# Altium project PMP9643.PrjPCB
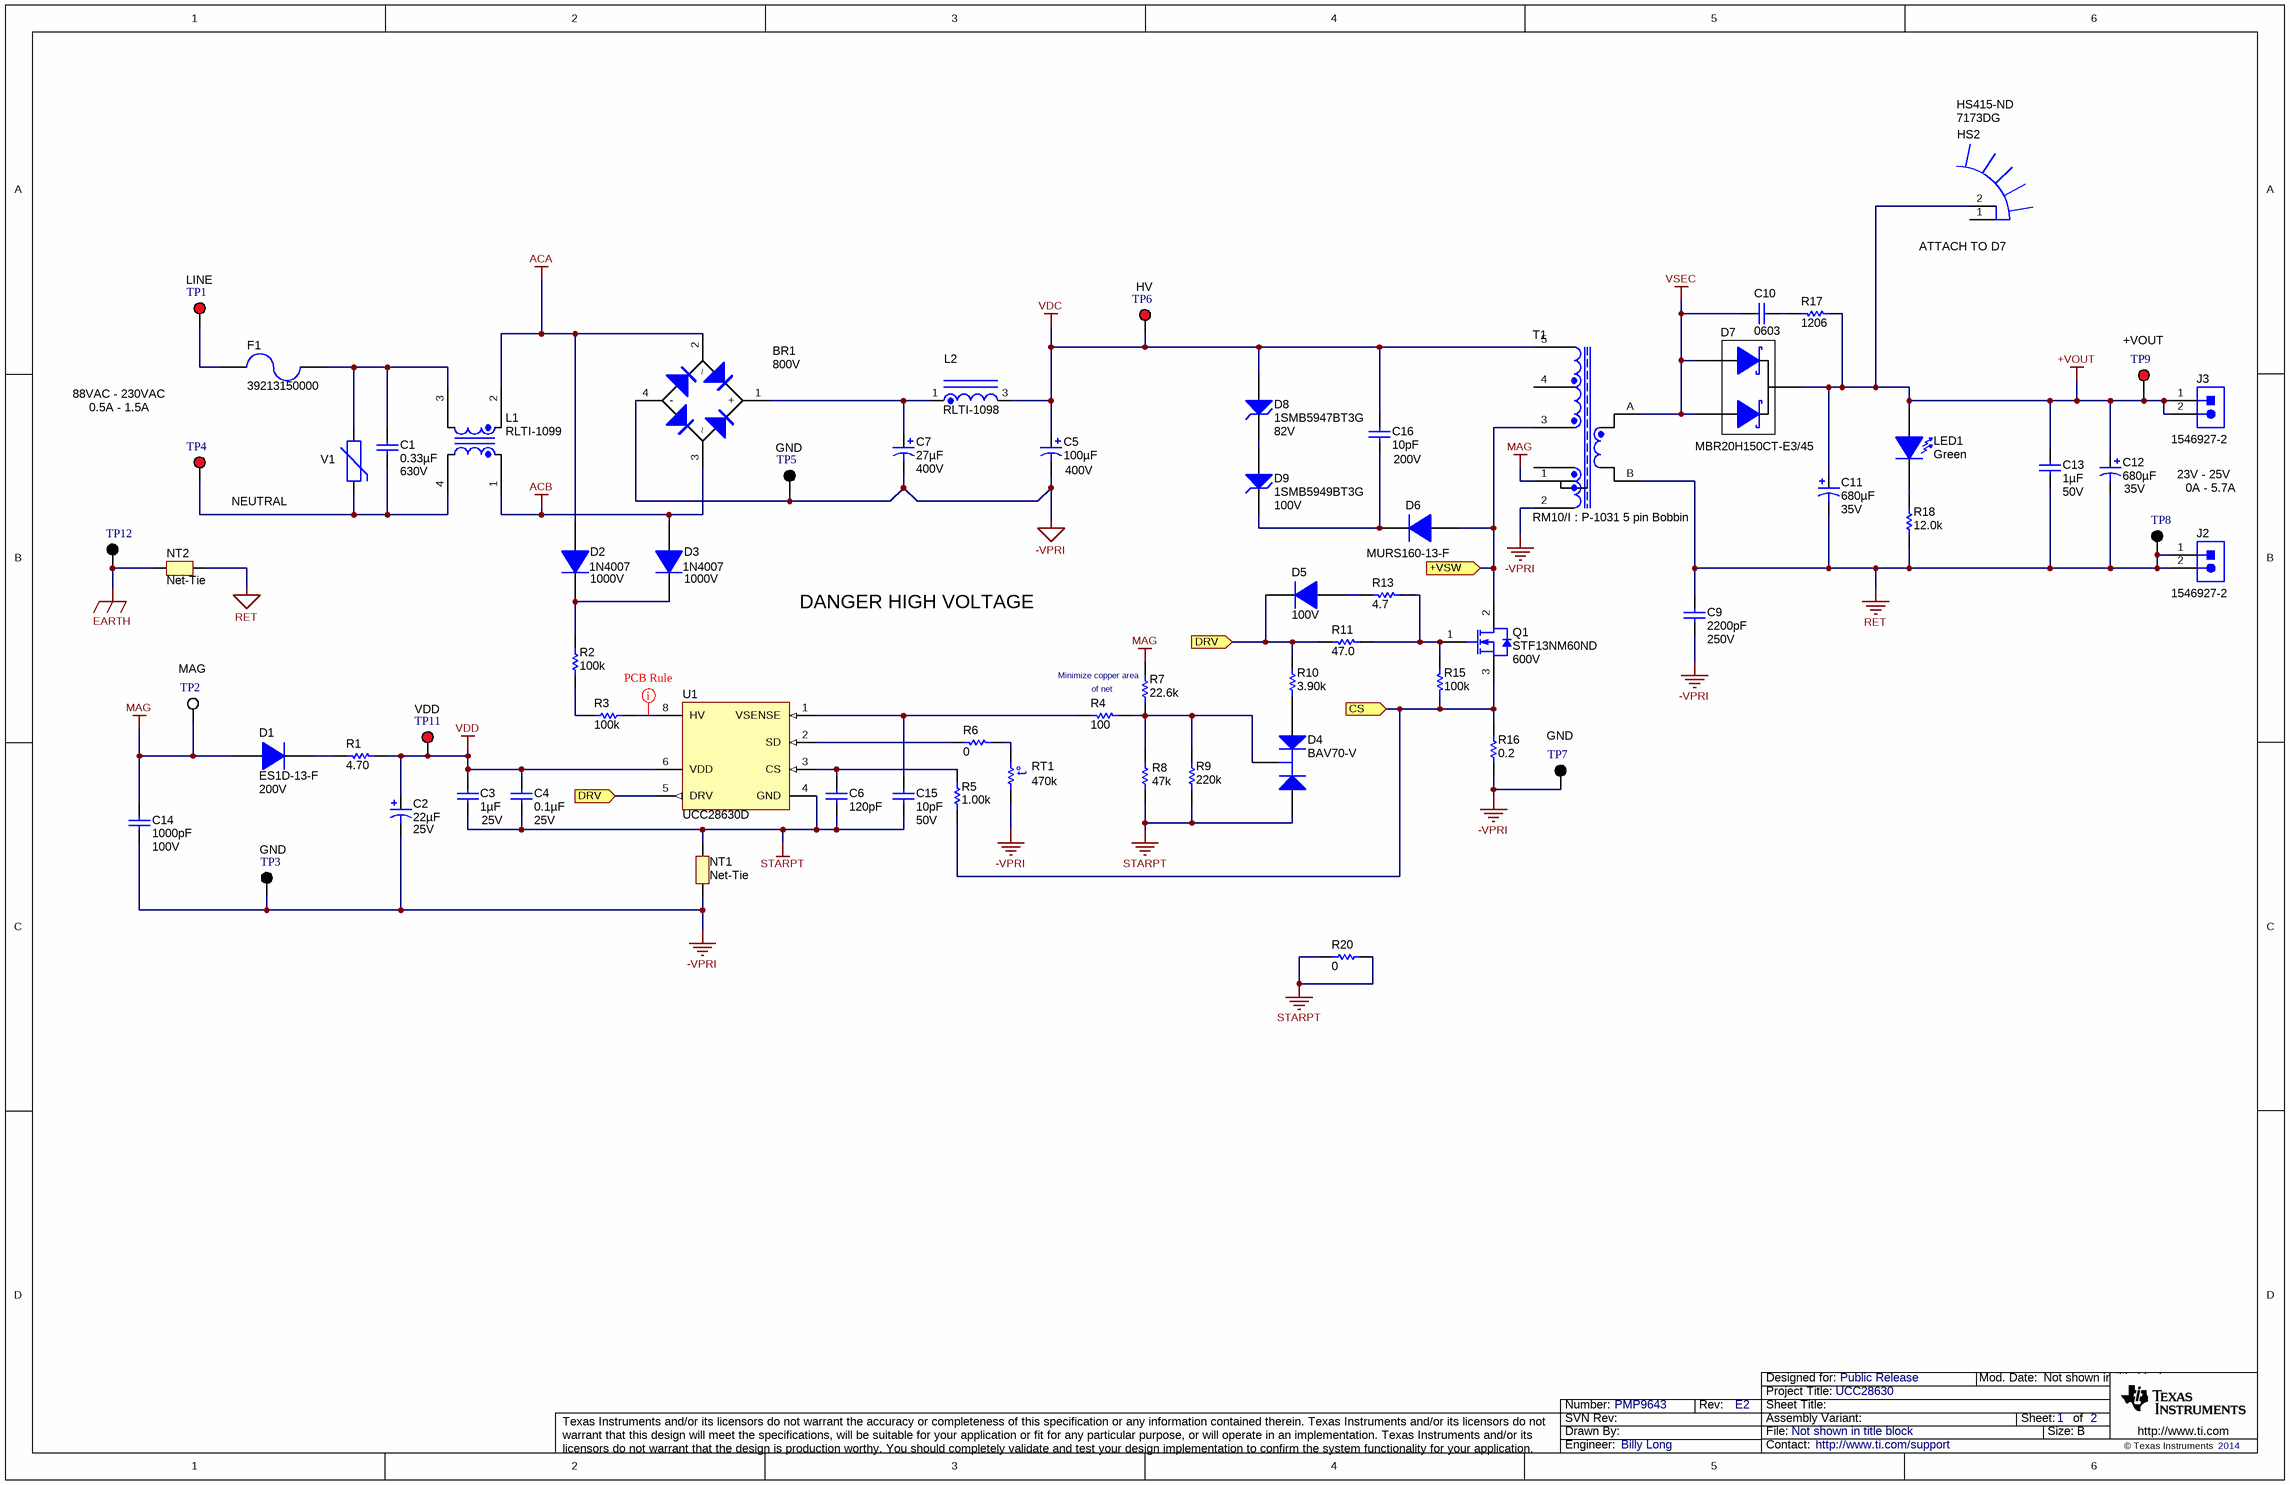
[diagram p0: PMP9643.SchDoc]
TechSupport: http://www.ti.com/support; SCH_Rev: E2; PRJ_Title: UCC28630; PRJ_Number: PMP9643; PRJ_Engineer: Billy Long; PRJ_Customer: Public Release; PCB_Rev: E2; PCB_Layout: Brian Gaynor; CopyrightYear: 2014
2 sheets, 91 parts. Net scope: flat (ports and power ports of the same name join across sheets).
Board file: PMP9643.PcbDoc
Sheets:
  PMP9643.SchDoc
  PMP9643HW.SchDoc

## Sheet PMP9643.SchDoc
size 431 x 279 mm; Date: Not shown in title block; ApprovedBy: Not shown in title block; CheckedBy: Not shown in title block; Author: Not shown in title block; CompanyName: Not shown in title block; Engineer: Not shown in title block; Organization: Not shown in title block; Address1: Not shown in title block; Address2: Not shown in title block; Address3: Not shown in title block; Address4: Not shown in title block; DocumentNumber: 1; Revision: Use project parameter SCH_Rev; SheetNumber: 1; SheetTotal: 2; PageSetup: Record=PageOptions|CenterHorizontal=True|CenterVertical=True|PrintScale=0.94|XCorrection=1.00|YCorrection=1.00|PrintKind=0|BorderSize=5000000|LeftOffset=0|BottomOffset=0|Orientation=2|PaperLength=4200|PaperWidth=2970|Scale=100|PaperSource=7|PrintQuality=600|MediaType=1|DitherType=10|PaperKind=A3|PrintScaleMode=1

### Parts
BR1  value 800V  [GBU]  (hidden comment: GBU4K-E3/45)
C1  ValueDisplayed: 0.33µF  Value2: 630V  [CAPRR1500W80D1750T1000H1650]  (hidden comment: BFC233840334)
C2  ValueDisplayed: 22µF  Value2: 25V  [ML_500x500]  (hidden comment: 25ML22MEFC5X5)
C3  ValueDisplayed: 1µF  Value2: 25V  [1206]  (hidden comment: 12063C105KAT2A)
C4  ValueDisplayed: 0.1µF  Value2: 25V  [0603]  (hidden comment: C0603C104K3RACTU)
C5  ValueDisplayed: 100µF  Value2: 400V  [CAPPR750W80D1600H3000]  (hidden comment: 400KXW100MEFC16X30)
C6  ValueDisplayed: 120pF  [0603]  (hidden comment: 06035A121JAT2A)
C7  ValueDisplayed: 27µF  Value2: 400V  [CY_1250x2000]  (hidden comment: UCY2G270MHD1TO)
C9  ValueDisplayed: 2200pF  Value2: 250V  [CAPRD1000W60D1000H1400]  (hidden comment: DE1E3KX222MA5BA01)
C10  0603YC823KAT2A  [0603]  (value not drawn)
C11  ValueDisplayed: 680µF  Value2: 35V  [HW_10x20]  (hidden comment: UHW1V681MPD6)
C12  ValueDisplayed: 680µF  Value2: 35V  [HW_10x20]  (hidden comment: UHW1V681MPD6)
C13  ValueDisplayed: 1µF  Value2: 50V  [0805_HV]  (hidden comment: 08055C105KAT2A)
C14  ValueDisplayed: 1000pF  Value2: 100V  [0805_HV]  (hidden comment: 08051C102KAT2A)
C15  ValueDisplayed: 10pF  Value2: 50V  [0603]  (hidden comment: 06035A100JAT2A)
C16  ValueDisplayed: 10pF  Value2: 200V  [1206]  (hidden comment: 12062A100JAT2A)
D1  value 200V  [SMA]  (hidden comment: ES1D-13-F)
D2  1N4007  value 1000V  [DO-41]
D3  1N4007  value 1000V  [DO-41]
D4  BAV70-V  [SOT-23]
D5  value 100V  [sod-323]  (hidden comment: BAS316,115)
D6  MURS160-13-F  [SMB]
D7  MBR20H150CT-E3/45  [TO-220AB_100mil]
D8  1SMB5947BT3G  value 82V  [SMB]
D9  1SMB5949BT3G  value 100V  [SMB]
F1  39213150000  [FUSE_392]
HS2  7173DG  Supplier Part Number 1: HS415-ND  [HSINK_7173DG]
J2  1546927-2  [TE-1546927-2]
J3  1546927-2  [TE-1546927-2]
L1  RLTI-1099  [RLTI-1099]
L2  RLTI-1098  [RLTI-1098]
LED1  value Green  [LED_HLMP1523]  (hidden comment: HLMP1523)
NT1  Net-Tie  [Net-Tie_10mil]  (net tie, no BOM)
NT2  Net-Tie  [Net-Tie_10mil]  (net tie, no BOM)
Q1  STF13NM60ND  value 600V  [TO-220_FullPAK_Offset]
R1  value 4.70  [0805_HV]  (hidden comment: ERJ-6RQF4R7V)
R2  value 100k  [1206]  (hidden comment: RC1206FR-07100KL)
R3  value 100k  [1206]  (hidden comment: RC1206FR-07100KL)
R4  value 100  [0603]  (hidden comment: CRCW0603100RFKEA)
R5  value 1.00k  [0603]  (hidden comment: CRCW06031K00FKEA)
R6  value 0  [0603]  (hidden comment: CRCW06030000Z0EA)
R7  value 22.6k  [1206]  (hidden comment: CRCW120622K6FKEA)
R8  value 47k  [1206]  (hidden comment: CRCW120647K0FKEA)
R9  value 220k  [0603]  (hidden comment: RC0603FR-07220KL)
R10  value 3.90k  [0603]  (hidden comment: RC0603FR-073K9L)
R11  value 47.0  [1206]  (hidden comment: RC1206FR-0747RL)
R13  value 4.7  [1206]  (hidden comment: CRCW12064R70JNEA)
R15  value 100k  [0603]  (hidden comment: CRCW0603100KFKEA)
R16  value 0.2  [2512M]  (hidden comment: CSRN2512FKR200)
R17  CRCW12061K00FKEA  [1206]  (value not drawn)
R18  value 12.0k  [1206]  (hidden comment: RC1206FR-0712KL)
R20  value 0  [1206]  (hidden comment: CRCW12060000Z0EA)
RT1  value 470k  [THERM_B57164K]  (hidden comment: B57164K474J)
T1  RM10/I : P-1031 5 pin Bobbin  [RM10-5pin]
TP1  5005  [Keystone5005]  (value not drawn)
TP2  5007  [Keystone5007]  (value not drawn)
TP3  5006  [Keystone5006]  (value not drawn)
TP4  5005  [Keystone5005]  (value not drawn)
TP5  5006  [Keystone5006]  (value not drawn)
TP6  5005  [Keystone5005]  (value not drawn)
TP7  5006  [Keystone5006]  (value not drawn)
TP8  5006  [Keystone5006]  (value not drawn)
TP9  5005  [Keystone5005]  (value not drawn)
TP11  5005  [Keystone5005]  (value not drawn)
TP12  5006  [Keystone5006]  (value not drawn)
U1  UCC28630D  [D0007A_N]
V1  B72214S0271K101  [VAR_B72214S0271]  (value not drawn)

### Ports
+VSW, CS, DRV

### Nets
+VOUT: C11.1(+) C12.1(+) C13.2 D7.2(K) HS2.2 J3.1 J3.2 LED1.1(A) R17.1 TP9.1
-VPRI: BR1.4(-) C2.2(-) C5.2(-) C7.2(-) C9.2 C14.2 NT1.2 R16.1 RT1.1 T1.2 TP3.1 TP5.1 TP7.1
ACA: BR1.2 D2.2(A) L1.2
ACB: BR1.3 D3.2(A) L1.1
EARTH: NT2.1 TP12.1
MAG: C14.1 D1.2(A) R7.1 T1.1 TP2.1
RET: C9.1 C11.2(-) C12.2(-) C13.1 J2.1 J2.2 NT2.2 R18.1 T1.B TP8.1
STARPT: C3.2 C4.2 C6.2 C15.1 D4.2(K) NT1.1 R8.1 R9.1 R20.1 R20.2 U1.4(GND)
VDC: C5.1(+) C16.2 D8.2(A) L2.3 T1.5 TP6.1
VDD: C2.1(+) C3.1 C4.1 R1.1 TP11.1 U1.6(VDD)
VSEC: C10.2 D7.1(A) D7.3(A) T1.A
+VSW: D6.2(A) Q1.2(D) T1.3 ; port +VSW
CS: Q1.3(S) R5.1 R15.1 R16.2 ; port CS
DRV: D5.1(K) R10.2 R11.2 U1.5(DRV) ; port DRV
NetBR1_1: BR1.1(+) C7.1(+) L2.1
NetC1_1: C1.1 L1.4 TP4.1 V1.2
NetC1_2: C1.2 F1.1 L1.3 V1.1
NetC6_1: C6.1 R5.2 U1.3(CS)
NetC10_1: C10.1 R17.2
NetC15_2: C15.2 R4.2 U1.1(VSENSE)
NetC16_1: C16.1 D6.1(K) D9.1(K)
NetD1_1: D1.1(K) R1.2
NetD2_1: D2.1(K) D3.1(K) R2.2
NetD4_1: D4.1(A) R10.1
NetD4_3: D4.3(C) R4.1 R7.2 R8.2 R9.2
NetD5_2: D5.2(A) R13.2
NetD8_1: D8.1(K) D9.2(A)
NetF1_2: F1.2 TP1.1
NetLED1_2: LED1.2(K) R18.2
NetQ1_1: Q1.1(G) R11.1 R13.1 R15.2
NetR2_1: R2.1 R3.2
NetR3_1: R3.1 U1.8(HV)
NetR6_1: R6.1 U1.2(SD)
NetR6_2: R6.2 RT1.2

Not connected (* = marked no-connect by the designer): HS2 1; T1 4

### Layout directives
rule Clearance Constraint [Clearance = 1mm]: NetR3_1

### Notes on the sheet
- (near TP1) LINE
- (near TP6) HV
- (near HS2) ATTACH TO D7
- (near TP9) +VOUT
- 88VAC - 230VAC
- 0.5A - 1.5A
- NEUTRAL
- GND
- 23V - 25V
- 0A - 5.7A
- DANGER HIGH VOLTAGE
- (near TP2) MAG
- (near TP11) VDD
- (near R7) Minimize copper area
- of net
- (near TP7) GND
- (near TP3) GND

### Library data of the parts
BR1 = GBU4K-E3/45: Diode, Switching-Bridge, 800V, 4A, TH; Manufacturer: Vishay-Semiconductor; U/M: EA; Vf_V: 1; Value2: 1V; Io_A: 4; Vr_V: 800; TJmax_C: 150; RJC_CperW: 4.2
C1 = BFC233840334: CAP, Film, 0.33uF, 630V, +/-20%, TH; Manufacturer: Vishay-Bccomponents; Polarized: N; CompType: Capacitor; U/M: EA; Cap_F: 0.00000033; Tolerance_%: 20; Value1: Unknown; VDC_V: 630; TaMin_C: -55; TaMax_C: 105; Cap_Case: 17.5x16.5x10mm
C2 = 25ML22MEFC5X5: CAP, AL, 22uF, 25V, +/-20%, TH; Manufacturer: Rubycon; Polarized: Y; CompType: Capacitor; U/M: EA; Cap_F: 0.000022; Tolerance_%: 20; Value1: Unknown; VDC_V: 25; IRMS_A: 0.042; TaMin_C: -40; TaMax_C: 105; Cap_Case: 5x5
C3 = 12063C105KAT2A: CAP, CERM, 1uF, 25V, +/-10%, X7R, 1206; Manufacturer: AVX; Polarized: N; CompType: Capacitor; U/M: EA; Cap_F: 0.000001; Tolerance_%: 10; ESR_Ohm: 0.013; Value1: 0.013 ohm; VDC_V: 25; TaMin_C: -55; TaMax_C: 125
C4 = C0603C104K3RACTU: CAP, CERM, 0.1uF, 25V, +/-10%, X7R, 0603; Manufacturer: Kemet; Polarized: N; CompType: Capacitor; U/M: EA; Cap_F: 0.0000001; Tolerance_%: 10; Value1: Unknown; VDC_V: 25; TaMin_C: -55; TaMax_C: 125
C5 = 400KXW100MEFC16X30: CAP, AL, 100uF, 400V, +/-20%, TH; Manufacturer: Rubycon; Polarized: Y; CompType: Capacitor; U/M: EA; Cap_F: 0.0001; Tolerance_%: 20; Value1: Unknown; VDC_V: 400; IRMS_A: 0.58; TaMin_C: -25; TaMax_C: 105; Cap_Case: RCAP, 16x30mm
C6 = 06035A121JAT2A: CAP, CERM, 120pF, 50V, +/-5%, C0G/NP0, 0603; Manufacturer: AVX; Polarized: N; CompType: Capacitor; U/M: EA; Cap_F: 0.00000000012; Tolerance_%: 5; ESR_Ohm: 0.109; Value1: 0.109 ohm; VDC_V: 50; TaMin_C: -55; TaMax_C: 125
C7 = UCY2G270MHD1TO: CAP, AL, 27uF, 400V, +/-20%, TH; Manufacturer: Nichicon; Tolerance_%: 20; VDC_V: 400; Polarized: Y; CompType: Capacitor; U/M: EA; Cap_F: 0.000027; Value1: Unknown; IRMS_A: 0.36; TaMin_C: -40; TaMax_C: 105; Cap_Case: 12.5x20
C9 = DE1E3KX222MA5BA01: CAP, CERM, 2200pF, 250V, +/-20%, E, Disc 10x8mm; Manufacturer: MuRata; VDC_V: 250; Tolerance_%: 20; Polarized: N; CompType: Capacitor; U/M: EA; Cap_F: 0.0000000022; Value1: Unknown; TaMin_C: -25; TaMax_C: 85
C10 = 0603YC823KAT2A: CAP, CERM, 0.082uF, 16V, +/-10%, X7R, 0603; Manufacturer: AVX; Polarized: N; CompType: Capacitor; ValueDisplayed: 0.082µF; U/M: EA; Cap_F: 0.000000082; Tolerance_%: 10; ESR_Ohm: 0.042; Value1: 0.042 ohm; VDC_V: 16; TaMin_C: -55; TaMax_C: 125
C11 = UHW1V681MPD6: CAP, AL, 680uF, 35V, +/-20%, 0.019 ohm, TH; Manufacturer: Nichicon; Tolerance_%: 20; VDC_V: 35; ESR_Ohm: 0.019; Polarized: Y; CompType: Capacitor; U/M: EA; Cap_F: 0.00068; IRMS_A: 2.5; TaMin_C: -40; TaMax_C: 105; Cap_Case: 10x20
C12 = UHW1V681MPD6: CAP, AL, 680uF, 35V, +/-20%, 0.019 ohm, TH; Manufacturer: Nichicon; Polarized: Y; CompType: Capacitor; U/M: EA; Cap_F: 0.00068; Tolerance_%: 20; VDC_V: 35; ESR_Ohm: 0.019; IRMS_A: 2.5; TaMin_C: -40; TaMax_C: 105; Cap_Case: 10x20
C13 = 08055C105KAT2A: CAP, CERM, 1uF, 50V, +/-10%, X7R, 0805; Manufacturer: AVX; Polarized: N; CompType: Capacitor; U/M: EA; Cap_F: 0.000001; Tolerance_%: 10; Value1: Unknown; VDC_V: 50; TaMin_C: -55; TaMax_C: 125; Cap_Case: 0805
C14 = 08051C102KAT2A: CAP, CERM, 1000pF, 100V, +/-10%, X7R, 0805; Manufacturer: AVX; Polarized: N; CompType: Capacitor; U/M: EA; Cap_F: 0.000000001; Tolerance_%: 10; ESR_Ohm: 0.29; Value1: 0.29 ohm; VDC_V: 100; TaMin_C: -55; TaMax_C: 125; Cap_Case: 0805
C15 = 06035A100JAT2A: CAP, CERM, 10pF, 50V, +/-5%, C0G/NP0, 0603; Manufacturer: AVX; Polarized: N; CompType: Capacitor; U/M: EA; Cap_F: 0.00000000001; Tolerance_%: 5; ESR_Ohm: 0.403; Value1: 0.403 ohm; VDC_V: 50; TaMin_C: -55; TaMax_C: 125
C16 = 12062A100JAT2A: CAP, CERM, 10pF, 200V, +/-5%, C0G/NP0, 1206; Manufacturer: AVX; Polarized: N; CompType: Capacitor; U/M: EA; Cap_F: 0.00000000001; Tolerance_%: 5; Value1: Unknown; VDC_V: 200; TaMin_C: -55; TaMax_C: 125
D1 = ES1D-13-F: Diode, Ultrafast, 200V, 1A, SMA; Manufacturer: Diodes Inc.; U/M: EA; Vf_V: 0.92; Value2: 0.92V; Io_A: 1; Vr_V: 200; TJmax_C: 150; RJC_CperW: 25
D2 D3 = 1N4007: Diode, P-N, 1000V, 1A, TH; Manufacturer: Fairchild Semiconductor; U/M: EA; Vf_V: 1.1; Value2: 1.1V; Io_A: 1; Vr_V: 1000; TJmax_C: 175; RJC_CperW: 50
D4 = BAV70-V: Diode, Switching, 70V, 0.25A, SOT-23; Manufacturer: Vishay-Semiconductor; SymbolCreator: a0412235; U/M: EA; Vf_V: 1.25; Value2: 1.25V; Io_A: 0.25; Vr_V: 70; TJmax_C: 150; RJC_CperW: 430
D5 = BAS316,115: Diode, Ultrafast, 100V, 0.25A, SOD-323; Manufacturer: NXP Semiconductor; U/M: EA; Vf_V: 1.4; Value2: 1.4V; Io_A: 0.25; Vr_V: 100; TJmax_C: 150
D6 = MURS160-13-F: Diode, Ultrafast, 600V, 1A, SMB; Manufacturer: Diodes Inc.; U/M: EA; Vf_V: 1.25; Value2: 1.25V; Io_A: 1; Vr_V: 600; TJmax_C: 150; RJC_CperW: 13
D7 = NTST30100CTG: Manufacturer: Vishay Semiconductor Diodes Division; Vr_V: 150V; Speed: Fast Recovery =< 500ns, > 200mA (Io); Type: Schottky; Value: 900mV @ 10A; Description: DIODE SCHOTTKY 150V 10A TO220AB; Diode Configuration: 1 Pair Common Cathode; Current - Reverse Leakage @ Vr: 5µA @ 150V; Current - Average Rectified (Io) (per Diode): 10A
D8 = 1SMB5947BT3G: Diode, Zener, 82V, 550mW, SMB; Manufacturer: ON Semiconductor; U/M: EA; Power_W: 0.55; Vz_V: 82; Value1: 0.55W; RJA_CperW: 226
D9 = 1SMB5949BT3G: Diode, Zener, 100V, 550mW, SMB; Manufacturer: ON Semiconductor; U/M: EA; Power_W: 0.55; Vz_V: 100; Value1: 0.55W; RJA_CperW: 226
F1 = 39213150000: Fuse, 3.15A, 250V, TH; Manufacturer: Littelfuse; U/M: EA; OpeningTime_200%_max: 120; VDC_V: 250; Irating_A: 3.15; Vdrop: 0.08; Soldering_Wave_MaxTemp_C: 260; Soldering_Wave_MaxTime_s: 5
HS2 = 7173DG: BOARD LEVEL HEATSINK .375" TO-220; Manufacturer: Aavid Thermalloy; Attachment Method: Bolt On and PC Pin; Material Finish: Tin; Thermal Resistance @ Natural: 25.8°C/W; Thermal Resistance @ Forced Air Flow: 10.0°C/W @ 200 LFM; Power Dissipation @ Temperature Rise: 1.5W @ 50°C; Shape: Rectangular
J2 J3 = TE-1546927-2: Manufacturer: TE Connectivity; Pitch: 0.325" (8.26mm); Number of Wire Entries: 2; Bottom Termination: PC Pin; Top Termination: Screws with Captive Plate; VDC_V: 300V; Material - Insulation: Polybutylene Terephthalate (PBT); Current Rating: 15A; Wire Gauge: 14-22 AWG; Material Flammability Rating: UL94 V-0; Barrier Type: 3 Wall (Tri); Description: CONN BARRIER BLOCK 2CIRC 8.26MM
L1 = RLTI-1099: Inductor, Toroid, ?, 4.5mH, A, 0.05 ohm, TH; Manufacturer: Renco Electronics; SymbolCreator: a0799628; Ind_H: 4.5E-3; Irms: 25A @ C rise; DCR_ohm: 0.05; U/M: EA
L2 = RLTI-1098: Inductor, Toroid, ?, 47.7uH, A, 0.04 ohm, TH; Manufacturer: Renco Electronics; ValueDisplayed: 47.7µH; SymbolCreator: x0208326; Ind_H: 47.7E-6; Irms: 25A @ C rise; DCR_ohm: 0.04; U/M: EA
LED1 = HLMP1523: LED, Green, TH; Manufacturer: Everlight; Vf_V: 2.2; Value2: 2.2V; Io_A: 0.02; Tjmax_C: 100; Value1: W; U/M: EA
NT1 NT2 = Net-Tie: Single point connection between nets.; SymbolCreator: codlsc
Q1 = STF13NM60ND: MOSFET, N-CH, 600V, 11A, TO-220 FullPAK; Manufacturer: ST Microelectronics; Alternate Manufacturer: None; U/M: EA; ChType: N; VdsMax_V: 600; Value1: ? ohm; Value2: 24.5 nC; QgTyp_nC: 24.5; Vgs_V: 25; IdsMax_A: 11
R1 = ERJ-6RQF4R7V: RES, 4.70 ohm, 1%, 0.125W, 0805; Manufacturer: Panasonic; CompType: Resistor; TempCo: 200 ppm/C; Tolerance_%: 1; Power_W: 0.125; Res_ohm: 4.7; Value_Code: 4R70; U/M: EA
R2 R3 = RC1206FR-07100KL: RES, 100k ohm, 1%, 0.25W, 1206; Manufacturer: Yageo America; CompType: Resistor; Res_ohm: 100000; Tolerance_%: 1; Power_W: 0.25; VDC_V: 200; TempCo: 100 ppm/C; EIA_Code: E96; U/M: EA
R4 = CRCW0603100RFKEA: RES, 100 ohm, 1%, 0.1W, 0603; Manufacturer: Vishay-Dale; CompType: Resistor; Value_Code: 100R; Tolerance_%: 1; Power_W: 0.1; VDC_V: 75; TempCo: 100 ppm/C; EIA_Code: E96; U/M: EA
R5 = CRCW06031K00FKEA: RES, 1.00k ohm, 1%, 0.1W, 0603; Manufacturer: Vishay-Dale; CompType: Resistor; Res_ohm: 1000; Value_Code: 1k00; Tolerance_%: 1; Power_W: 0.1; VDC_V: 75; TempCo: 100 ppm/C; EIA_Code: E96; U/M: EA
R6 = CRCW06030000Z0EA: RES, 0 ohm, 5%, 0.1W, 0603; Manufacturer: Vishay-Dale; CompType: Resistor; Value_Code: 0000; Tolerance_%: 5; Power_W: 0.1; VDC_V: 75; TempCo: 200 ppm/C; EIA_Code: E24; U/M: EA
R7 = CRCW120622K6FKEA: RES, 22.6k ohm, 1%, 0.25W, 1206; Manufacturer: Vishay-Dale; CompType: Resistor; Res_ohm: 22600; Value_Code: 22k6; Tolerance_%: 1; Power_W: 0.25; VDC_V: 200; TempCo: 100 ppm/C; EIA_Code: E96; U/M: EA
R8 = CRCW120647K0JNEA: RES, 47k ohm, 5%, 0.25W, 1206; Manufacturer: Vishay Dale; Description: RES 47.0K OHM 1/4W 1% 1206 SMD; Tolerance_%: ±1%; Power_W: 0.25W, 1/4W; TempCo: ±100ppm/°C
R9 = RC0603FR-07220KL: RES, 220k ohm, 1%, 0.1W, 0603; Manufacturer: Yageo America; TempCo: 200 ppm/C; Power_W: 0.1; Tolerance_%: 1; CompType: Resistor; Res_ohm: 220000; VDC_V: 150; U/M: EA
R10 = RC0603FR-073K9L: RES, 3.90k ohm, 1%, 0.1W, 0603; Manufacturer: Yageo America; CompType: Resistor; Res_ohm: 3900; Value_Code: 3k90; Tolerance_%: 1; Power_W: 0.1; VDC_V: 150; TempCo: 200 ppm/C; U/M: EA
R11 = RC1206FR-0747RL: RES, 47.0 ohm, 1%, 0.25W, 1206; Manufacturer: Yageo America; CompType: Resistor; Res_ohm: 47; Value_Code: 47R0; Tolerance_%: 1; Power_W: 0.25; VDC_V: 200; TempCo: 100 ppm/C; U/M: EA
R13 = CRCW12064R70JNEA: RES, 4.7 ohm, 5%, 0.25W, 1206; Manufacturer: Vishay-Dale; CompType: Resistor; Value_Code: 4R70; Tolerance_%: 5; Power_W: 0.25; VDC_V: 200; TempCo: 200 ppm/C; EIA_Code: E24; U/M: EA
R15 = CRCW0603100KFKEA: RES, 100k ohm, 1%, 0.1W, 0603; Manufacturer: Vishay-Dale; CompType: Resistor; Res_ohm: 100000; Tolerance_%: 1; Power_W: 0.1; VDC_V: 75; TempCo: 100 ppm/C; EIA_Code: E96; U/M: EA
R16 = CSRN2512FKR200: RES, 0.2 ohm, 1%, 2W, 2512; Manufacturer: Stackpole Electronics Inc; CompType: Resistor; Value_Code: R200; Tolerance_%: 1; Power_W: 2; TempCo: 200 ppm/C; EIA_Code: E96; U/M: EA
R17 = CRCW12061K00FKEA: RES, 1.00k ohm, 1%, 0.25W, 1206; Manufacturer: Vishay-Dale; CompType: Resistor; Res_ohm: 1000; Value_Code: 1k00; Tolerance_%: 1; Power_W: 0.25; VDC_V: 200; TempCo: 100 ppm/C; EIA_Code: E96; U/M: EA
R18 = RC1206FR-0712KL: RES, 12.0k ohm, 1%, 0.25W, 1206; Manufacturer: Yageo America; CompType: Resistor; Res_ohm: 12000; Value_Code: 12k0; Tolerance_%: 1; Power_W: 0.25; VDC_V: 200; TempCo: 100 ppm/C; U/M: EA
R20 = CRCW12060000Z0EA: RES, 0 ohm, 5%, 0.25W, 1206; Manufacturer: Vishay-Dale; CompType: Resistor; Value_Code: 0000; Tolerance_%: 5; Power_W: 0.25; VDC_V: 200; TempCo: 200 ppm/C; EIA_Code: E24; U/M: EA
RT1 = B57164K474J: Thermistor NTC, 470k ohm, 5%, Disc, 5.5x5mm; Manufacturer: EPCOS Inc; Tolerance_%: 5; Power_W: 0.45; TaMin_C: -55; TaMax_C: 125; U/M: EA
T1 = RM10-5pin
TP1 TP4 TP6 TP9 TP11 = 5005: Test Point, Compact, Red, TH; Manufacturer: Keystone; CompType: Test Point Loop; U/M: EA
TP2 = 5007: Test Point, Compact, White, TH; Manufacturer: Keystone; CompType: Test Point Loop; U/M: EA
TP3 TP5 TP7 TP8 TP12 = 5006: Test Point, Compact, Black, TH; Manufacturer: Keystone; CompType: Test Point Loop; U/M: EA
U1 = UCC28630D: Green-Mode Flyback Controller, D0007A; Alternate Manufacturer: None; Manufacturer: Texas Instruments; SymbolCreator: a0411947; CompType: IC; U/M: EA
V1 = B72214S0271K101: Varistor, 430V, 4.5KA, TH; Manufacturer: EPCOS Inc; SymbolCreator: a0412235

## Sheet PMP9643HW.SchDoc
size 431 x 279 mm; Date: Not shown in title block; ApprovedBy: Not shown in title block; CheckedBy: Not shown in title block; Author: Not shown in title block; CompanyName: Not shown in title block; Engineer: Not shown in title block; Organization: Not shown in title block; Address1: Not shown in title block; Address2: Not shown in title block; Address3: Not shown in title block; Address4: Not shown in title block; DocumentNumber: 1; Revision: Use project parameter SCH_Rev; SheetNumber: 2; SheetTotal: 2; PageSetup: Record=PageOptions|CenterHorizontal=True|CenterVertical=True|PrintScale=1.00|XCorrection=1.00|YCorrection=1.00|PrintKind=0|BorderSize=5000000|LeftOffset=0|BottomOffset=0|Orientation=2|PaperLength=1000|PaperWidth=1000|Scale=100|PaperSource=15|PrintQuality=600|MediaType=1|DitherType=10|PaperKind=Letter|PrintScaleMode=1
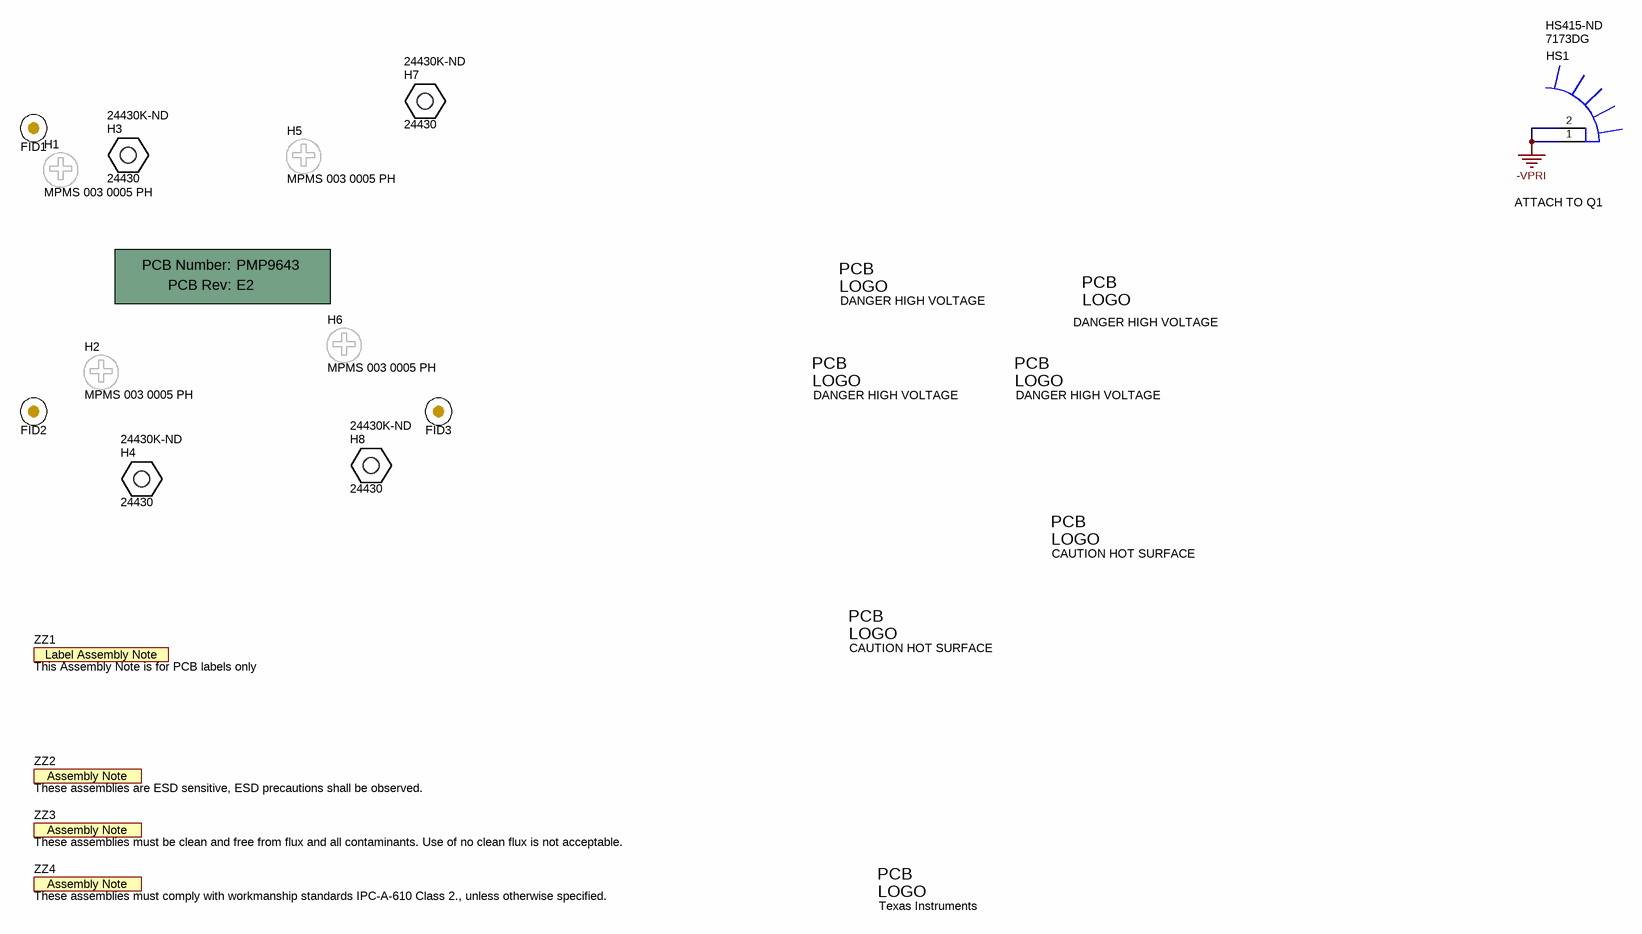
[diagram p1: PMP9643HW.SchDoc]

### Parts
!PCB1  Printed Circuit Board  (value not drawn)  (mechanical)
FID1  Fiducial  [Fiducial10-20]  (value not drawn)
FID2  Fiducial  [Fiducial10-20]  (value not drawn)
FID3  Fiducial  [Fiducial10-20]  (value not drawn)
H1  MPMS 003 0005 PH  [BuildingFastener_MPMS_003_0005_PH]
H2  MPMS 003 0005 PH  [BuildingFastener_MPMS_003_0005_PH]
H3  24430  Supplier Part Number: 24430K-ND  [Keystone_24430]
H4  24430  Supplier Part Number: 24430K-ND  [Keystone_24430]
H5  MPMS 003 0005 PH  [BuildingFastener_MPMS_003_0005_PH]
H6  MPMS 003 0005 PH  [BuildingFastener_MPMS_003_0005_PH]
H7  24430  Supplier Part Number: 24430K-ND  [Keystone_24430]
H8  24430  Supplier Part Number: 24430K-ND  [Keystone_24430]
HS1  7173DG  Supplier Part Number 1: HS415-ND  [HSINK_7173DG]
Logo2  DANGER HIGH VOLTAGE  [IEC_HighVoltage_Small]  (no BOM)
Logo3  DANGER HIGH VOLTAGE  [IEC_HighVoltage_Small]  (no BOM)
Logo4  DANGER HIGH VOLTAGE  [IEC_HighVoltage_Small]  (no BOM)
Logo5  CAUTION HOT SURFACE  [IEC_HotSurface_Small]  (no BOM)
Logo7  Texas Instruments  [TI_Stacked_Overlay_Medium]  (no BOM)
Logo8  DANGER HIGH VOLTAGE  [IEC_HighVoltage_Small]  (no BOM)
Logo9  CAUTION HOT SURFACE  [IEC_HotSurface_Small]  (no BOM)
ZZ1  This Assembly Note is for PCB labels only  [AssemblyNoteLabel]  (no BOM)
ZZ2  These assemblies are ESD sensitive, ESD precautions shall be observed.  [AssemblyNote]  (no BOM)
ZZ3  These assemblies must be clean and free from flux and all contaminants. Use of no clean flux is not acceptable.  [AssemblyNote]  (no BOM)
ZZ4  These assemblies must comply with workmanship standards IPC-A-610 Class 2., unless otherwise specified.  [AssemblyNote]  (no BOM)

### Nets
-VPRI: HS1.1 HS1.2

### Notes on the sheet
- ATTACH TO Q1

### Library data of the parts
!PCB1 = PCB: Manufacturer: Any; PartNumber: PMP9643; SymbolCreator: a0412235
FID1-FID3 = Fiducial: Fiducial mark.  There is nothing to buy or mount.; SymbolCreator: codlsc
H1 H2 H5 H6 = MPMS 003 0005 PH: MACHINE SCREW PAN PHILLIPS M3; Manufacturer: B&F Fastener Supply; CompType: Hardware
H3 H4 H7 H8 = 1902C: HEX STANDOFF M3 ALUMINUM 5MM; Manufacturer: Keystone Electronics; Threaded/Unthreaded: Threaded; Gender: Female, Female; Thread/Screw/Hole Size: M3 Thread; Between Board Height: 0.197" (5.00mm); Plating: Iridite
HS1 = 7173DG: as HS2 on sheet PMP9643
Logo2-Logo4 Logo8 = IEC_HighVoltage: IEC 61010-1 High Voltage Warning; SymbolCreator: codlsc
Logo5 Logo9 = IEC_HotSurface: IEC 61010-1 Hot Surface Warning; SymbolCreator: codlsc
Logo7 = TI_Logo: Texas Instrument Corporate Signature; SymbolCreator: codlsc
ZZ1 = AssemblyNoteLabel: SymbolCreator: a0412235
ZZ2-ZZ4 = AssemblyNote: SymbolCreator: codlsc

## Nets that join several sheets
-VPRI: PMP9643 (13 pins), PMP9643HW (HS1.1 HS1.2)

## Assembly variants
001: not fitted C8 C10 D10 FID1 FID2 FID3 R12 R17
002: all parts fitted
